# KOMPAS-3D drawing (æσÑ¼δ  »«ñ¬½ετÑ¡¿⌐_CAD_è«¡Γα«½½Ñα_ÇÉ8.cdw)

Views: Вид 1, Спереди, Спереди 2, Проекционный вид 3
Referenced files in D:\Фрагменты для КОМПАС\Элементы для схем\: разъем вилка.frw, разъем гнездо.frw
Referenced files in F:\19032019_ДокументыАР8\11032019_Комплект_КД_с_моделями\Users\Buhalov\Documents\: USB.bmp, clipart-ethernet-connector-symbol-big-image-png_connector-symbol_symbol-for-resistance-wire-circuit-electronics-componen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
Referenced files in D:\Рабочая папка\Новое\KSB_Наш_Контроллер\ВЫХОД\КД\11032019_Комплект_КД_с_моделями\КНМБ_424318_050_КД\: Технологическая_сборка_АР8_v2_0.t3d
Referenced files in D:\Рабочая папка\Новое\KSB_Наш_Контроллер\ВЫХОД\КД\11032019_Комплект_КД_с_моделями\КНМБ_424318_050_КД\Эксплуатационная_документация_(ЭД)\: Схемы  подключений_CAD_Контроллер_АР8.cdw
Referenced files in D:\Рабочая папка\Новое\KSB_Наш_Контроллер\ВЫХОД\КД\11032019_Комплект_КД_с_моделями\Исходные данные\KSB\: Board.m3d, SO18.m3d, DD7.a3d, SOT-23.m3d, VT7.a3d, CE050M0220REG-1010.m3d, C16.a3d, 2EDGRС-5.0-03P-14.m3d, XS8.a3d, XS9.a3d, 2EDGRС-5.0-02P-14.m3d, XS5.a3d, XS2.a3d, XS13.a3d, XS12.a3d, 2EDGRС-5.0-04P-14.m3d, XS11.a3d, XS10.a3d, SRU5028.m3d, L2.a3d, EDR101A.m3d, K1.a3d, DS1092-12-N8S.m3d, GB1.a3d, C-TYPE_A.m3d, C18.a3d, C17.a3d, Extruded.m3d, 981821032.a3d, Extruded_1.m3d, 981821168.a3d, C11.a3d, C9.a3d, C5.a3d, Extruded_2.m3d, 981821304.a3d, Extruded_3.m3d, 981821440.a3d, C4.a3d, User_Library-IDC-14MS_Pin_1_____________.m3d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
Referenced files in D:\Рабочая папка\Новое\KSB_Наш_Контроллер\ВЫХОД\КД\11032019_Комплект_КД_с_моделями\Исходные данные\Винты гайки шайбы\: Стойка_11мм_М3.m3d, Шайба_М3_DIN125.m3d, Шайба_гроверная_М3_DIN127.m3d, Винт_М3х6_DIN7985.m3d, Саморез_М2,5х6.m3d
Referenced files in D:\Рабочая папка\Новое\KSB_Наш_Контроллер\ВЫХОД\КД\11032019_Комплект_КД_с_моделями\Исходные данные\Батарейка\: CR1220.m3d
Referenced files in D:\Рабочая папка\Новое\KSB_Наш_Контроллер\ВЫХОД\КД\11032019_Комплект_КД_с_моделями\Исходные данные\OrangePI\: Orange-pi-one-board.m3d, inductance.m3d, MicroUSB-B_Molex_105017-0001.m3d, hdmi.m3d, User Library-RMS-001L-08A0-GY_SignalPin.m3d, User Library-RMS-001L-08A0-GY_MechPin.m3d, User Library-RMS-001L-08A0-GY_LEDpin.m3d, User Library-RMS-001L-08A0-GY_CasePin.m3d, User Library-RMS-001L-08A0-GY_body.m3d, User Library-RMS-001L-08A0-GY.a3d, Allwinner-H3.m3d, PLS-1.m3d, USB_Defaut.m3d, MEM2055-00-190-01-A_revG.m3d, PLD-40.m3d, power-connector.m3d, SAMSUNG.m3d, Pushbutton - dik.m3d, Orange-pi-one.a3d
Referenced files in D:\Рабочая папка\Новое\KSB_Наш_Контроллер\ВЫХОД\КД\11032019_Комплект_КД_с_моделями\Исходные данные\microSD_card\micro-sd-slot-with-sd-card.snapshot.2 (1)\: sd.m3d
Referenced files in D:\Рабочая папка\Новое\KSB_Наш_Контроллер\ВЫХОД\КД\11032019_Комплект_КД_с_моделями\Исходные данные\Корпус\: Корпус_низ.m3d, Корпус_верх.m3d
Referenced files in D:\Рабочая папка\Новое\KSB_Наш_Контроллер\ВЫХОД\КД\11032019_Комплект_КД_с_моделями\Исходные данные\Клеммы\2\: 2EGDK-5.08-02P.m3d
Referenced files in D:\Рабочая папка\Новое\KSB_Наш_Контроллер\ВЫХОД\КД\11032019_Комплект_КД_с_моделями\Исходные данные\Клеммы\3\: 2EGDK-5.08-03P.m3d
Referenced files in D:\Рабочая папка\Новое\KSB_Наш_Контроллер\ВЫХОД\КД\11032019_Комплект_КД_с_моделями\Исходные данные\Клеммы\5\: 2EGDK-5.08-05P.m3d
Referenced files in D:\Рабочая папка\Новое\KSB_Наш_Контроллер\ВЫХОД\КД\11032019_Комплект_КД_с_моделями\Исходные данные\Клеммы\4\: 2EGDK-5.08-04P.m3d
Referenced files in D:\Рабочая папка\Новое\KSB_Наш_Контроллер\ВЫХОД\КД\11032019_Комплект_КД_с_моделями\Исходные данные\Клеммы\9\: 2EGDK-5.08-09P.a3d
Referenced files in D:\Рабочая папка\Новое\KSB_Наш_Контроллер\ВЫХОД\КД\11032019_Комплект_КД_с_моделями\Исходные данные\SMA\: Sma female connector.m3d, Nuts etc_Shayba.m3d, Nuts etc_Grover.m3d, Nuts etc_Gayka.m3d
Referenced files in D:\Рабочая папка\Новое\KSB_Наш_Контроллер\ВЫХОД\КД\11032019_Комплект_КД_с_моделями\Исходные данные\SMA_antena\sma-antenna\: GSM_ANT_RA_SMA.m3d, GSM_ANT_WHIP.m3d, GSM_ANTENNA_900MHZ.a3d
Referenced files in D:\Рабочая папка\Новое\KSB_Наш_Контроллер\ВЫХОД\КД\11032019_Комплект_КД_с_моделями\Исходные данные\Модем_SIM800L\: Модем_SIM800L_V2.0_плата.m3d, CircuitWorks-HEADER 2_54 VERTICAL 5X.m3d, CircuitWorks-HEADER 2_54 VERTICAL 2X.m3d, Модем_SIM800L.a3d
Referenced files in D:\Рабочая папка\Новое\KSB_Наш_Контроллер\ВЫХОД\КД\11032019_Комплект_КД_с_моделями\Исходные данные\Радиомодем433\: Радиомодем433_HC11_HC12.m3d, CircuitWorks-HEADER 2_54 VERTICAL 5X.m3d, Радиомодем433_со_штырьками_сборка.a3d
Referenced files in D:\Рабочая папка\Новое\KSB_Наш_Контроллер\ВЫХОД\КД\11032019_Комплект_КД_с_моделями\Исходные данные\Этикетки\: Этикетка_лицевая.m3d, Маркировка_шильдик.m3d, Маркировка_Верх.m3d, Маркировка_Низ.m3d, Маркировка_ANT.m3d, Маркировка_HDMI_USB2.m3d, Гарантийная_пломба_microSD.m3d, Маркировка_ОТК.m3d
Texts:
  Buhalov
  ESKD1
  POLYLINE_STYLE_0.35_RGB_0_127_0
  Чертеж 1. Расположение клемм и разъемов на контроллере
  LAN
  USB
  RS-232
  GND
  OUT
  NO1
  NO2
  NO3
  NO4
  NO5
  NO6
  NO7
  NC7
  DI1
  DI2
  DI3
  DI4
  DI5
  DI6
  DI7
  DI8
  COM
  NO8
  NC8
  Индикатор питания (Желтый)
  Индикатор работы (Зеленый)
  Разъем антенны
  USB2
  HDMI
  ПЛК АР-8
  (DB9-M)
  GSM
  (SMA-F)
  USB 2.0
  (USB-A)
  RS485-1
  RS485-2
  Замкнут
  после запуска
  контроллера
  DCON
  (micro B)
  (RJ-45)
  Ethernet
  ИП2
  Общий выходов 1,2,3
  Выход 1
  Выход 2
  Выход 3
  Общий выходов 4,5,6
  Выход 4
  Выход 5
  Выход 6
  Выход 7 НО
  Общий выхода 7
  Выход 7 НЗ
  Выход 8 НО
  Общий выхода 8
  Выход 8 НЗ
  ИП1, ИП2 - источники питания
  U1, U2, U3, U4 - источники питания,
  могут быть объеденены
  Питание
  ИП1
  Нагрузка
  ИП - источник питания
  Конт.
  Gill Sans Ultra Bold
  Назначение
  Корпус
  RTS
  CTS
  Назначение контактов разъема DB9M
  Кабель
  К локально-вычислительной сети (ЛВС)
  Устройство
  Rок
  Типовое значение:
  Кабель UTP cat.5e
  монитор
  Сенсорная
  панель
  или другие USB
  устроства
  USB-Ethernet
  адаптер
  USB - Wi-Fi
  модем
  Wi-Fi
  к ЛВС
  Прямое подклчюение или через кабель
  DCON - разъеденитель питания
  антенна
  Граница
  Контроллер АР8
  Схемы  подключений
  Бухалов
  Горбунов
  Якимов
  Андреев
  ООО "НПО"Каскад-ГРУП"
  Без основной надписи.
  Board
  SO18
  DD7
  SOT-23
  VT7
  CE050M0220REG-1010
  XS8
  XS9
  XS5
  XS2
  XS13
  XS12
  XS11
  XS10
  SRU5028
  EDR101A
  DS1092-12-N8S
  GB1
  C-TYPE_A
  Extruded
  User_Library-IDC-14MS_Pin_1_____________
  User_Library-IDC-14MS_Case_IDC-14MS_____________
  IDC-14MS
  XP2
  VT1
  SMB
  VD8
  MiniMELF_SOD-80
  VD3
  DA4
  PLS-3R
  XP1
  PBS-5_(DS-1023_-1x5)
  XS7
  MF-MSMF
  FU5
  FU4
  FU3
  FU2
  DS1040
  SA1
  SIP4(stand)
  TO263-5-1
  DA1
  SO16
  DA2
  DA3
  DD2
  DD3
  DD4
  DD5
  DD6
  Jumper
  SRP1265A
  DD1
  VT3
  Поверхности
  VD2
  L-934GD_G
  VD4
  VD6
  VD9
  VD10
  VD11
  VD12
  VD13
  VD14
  VD15
  VD16
  VD17
  VT2
  VT4
  VT5
  VT6
  VT8
  VT10
  VT11
  VT12
  DRB-9MA
  XP3
  PBS-7_(DS1023-1x7)
  XS4
  PBS-3_(DS-1023_-_1x3)
  XS3
  VD1
  VD7
  PBD-40_(DS1023-2X20)
  XS1
  HF41F
  VD18
  VD19
  VD20
  L-934YD
  VD5
  MF-R135
  FU1
  XS6
  VT9
  Плата KSB rev 2.0
  KSB rev. 2.0
  Стойка М3 11 мм
  Стойка М3 L=11мм
  Батарейка CR1220
  Шайба М3
  Шайба гроверная М3
  Винт М3х6
  Orange-pi-one-board
  inductance
  MicroUSB-B_Molex_105017-0001
  hdmi
  User Library-RMS-001L-08A0-GY_SignalPin
  User Library-RMS-001L-08A0-GY_MechPin
  User Library-RMS-001L-08A0-GY_LEDpin
  User Library-RMS-001L-08A0-GY_CasePin
  User Library-RMS-001L-08A0-GY_body
  User Library-RMS-001L-08A0-GY
  Allwinner-H3
  PLS-1
  MEM2055-00-190-01-A_revG
  PLD-40
  power-connector
  SAMSUNG
  Pushbutton - dik
  Микрокомпьютер Orange Pi One
  Micro SD карта
  Mocro SD карта
  Корпус(основание)
  SANHE 23-66A (основание)
  Корпус(крышка)
  SANHE 23-66A (крышка)
  SMA разъем
  SMA разъем на корпус
  SMA шайба стопорная
  SMA гроверная шайба
  SMA гайка
  Антенна GSM/433МГц
  CircuitWorks-HEADER 2_54 VERTICAL 5X
  CircuitWorks-HEADER 2_54 VERTICAL 2X
  Модем SIM800L V2.0
  Саморез М2,5х6
  Радиомодем 433Мгц
  Этикетка лицевая
  Шильдик
  Маркировка верх
  Маркировка низ
  Маркировка SMA
  Маркировка HDMI_USB2
  Гарантийная пломба
  Этикетка ОТК
  Контроллер АР-8
  КНМБ.424318.050
  Сборочный вид
Dimensions and other numbers on the sheet: 24В; 1; 2; 3; 4; 5; 6; 7; 8; 9; 3G/4G USB; 3G/4G; 1:1; 2EDGRС-5.0-03P-14; 2EDGRС-5.0-02P-14; 2EDGRС-5.0-04P-14; 8SO-EP; 2EDGRС-5.0-09P-14; 2EGDK-5.0-02P; 2EGDK-5.0-03P; 2EGDK-5.08-05P; 2EGDK-5.08-04P; 2EGDK-5.0-09P; 2EGDK-5.0-04P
